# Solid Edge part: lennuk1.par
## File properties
Author: Priit
Template: Normal.par
Last saved by: Priit
Revision: 4
Application: Solid Edge
Accuracy: 0,990
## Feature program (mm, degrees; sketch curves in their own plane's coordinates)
sketch for "unnamed RevolvedProtrusion 1" plane through (0, 0, 0) normal (0, -1, 0) x-axis (1, 0, 0)
  bspline degree 3 poles (93.0645, 0) (25.9308, 33.3333) (-41.203, 33.3333) (-108.3368, 0) knots 0 1 multiplicities 4 4
  line (-108.3368, 0) -> (93.0645, 0)
revolve "unnamed RevolvedProtrusion 1" add finite 360 deg
lofted protrusion "unnamed LoftedProtrusion 1"
mirror "unnamed Mirror 1" of "unnamed LoftedProtrusion 1" about plane through (0, 0, 0) normal (0, -1, 0)
lofted protrusion "unnamed LoftedProtrusion 2"
lofted protrusion "unnamed LoftedProtrusion 3"
sketch used by "ExtrudedCutout_3" plane through (0, 0, 0) normal (0, -1, 0) x-axis (1, 0, 0)
extrude "ExtrudedCutout_3" cut finite 173.642 symmetric
sketch for "unnamed RevolvedCutout 1" plane through (0, 0, 0) normal (0, -1, 0) x-axis (1, 0, 0)
revolve "unnamed RevolvedCutout 1" cut finite 360 deg
sketch used by "ExtrudedCutout_5" plane through (0, 0, 0) normal (1, 0, 0) x-axis (0, 1, 0)
extrude "ExtrudedCutout_5" cut finite 149.25 along +normal
sketch for "ExtrudedProtrusion_1" plane through (-67.1627, -58.1792, 4) normal (-0.104528, -0.994522, 0) x-axis (0.993755, -0.104448, -0.039258)
  line (-13.2133, 2.9809) -> (11.7499, 4.4524)
  line (12.2198, -3.5199) -> (-13.0759, -4.0164)
extrude "ExtrudedProtrusion_1" add finite 4 along +normal
mirror "unnamed Mirror 2" of "ExtrudedProtrusion_1" about plane through (0, 0, 0) normal (0, -1, 0)
extrude "unnamed Protrusion 1" add finite 4
sketch for "ExtrudedCutout_6" plane through (0, 0, 0) normal (1, 0, 0) x-axis (0, 1, 0)
  circle centre (-31.8247, -0.6659) radius 2.0832
extrude "ExtrudedCutout_6" cut finite 26.1293 along -normal
mirror "unnamed Mirror 3" of "ExtrudedCutout_6" about plane through (0, 0, 0) normal (0, -1, 0)
extrude "unnamed Cutout 1" cut finite 26.1293
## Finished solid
Body 1: solid body, 38 faces, 91 edges, 58 vertices.
  Faces by surface: plane 16, spline 12, cylinder 7, spun 2, swept 1
  Edges by curve: line 32, intersection 30, circle 17, spline 12
Bounding box of the edges (mm; curved faces can reach further): 180.651 x 127.707 x 49.468, from (-99.7486, -63.8537, -4.4682) to (80.9029, 63.8537, 45).
Cylindrical faces by radius (mm): R2.0832 x2, R3.5 x2, R4 x2, R20.467 x1
Planar faces by outward normal: +x 2, +z 2, oblique 12
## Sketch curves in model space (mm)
circle centre (0, -31.8247, -0.6659) radius 2.0832
line (0, 7.2862, 19.1262) -> (0, 9.496, 5.6737)
arc centre (0, 0, 0) radius 20.467 from (0, -7.2862, 19.1262) through (0, 0, 20.467) to (0, 7.2862, 19.1262)
line (0, -7.2862, 19.1262) -> (0, -9.496, 5.6737)
line (0, -9.496, 5.6737) -> (0, 9.496, 5.6737)
line (-102.1983, 0, 0) -> (85.7441, 0, 0)
spline (-102.1983, 0, 0) -> (-7.9163, 0, 21.9859) -> (85.7441, 0, 0)
arc centre (-84.2075, 0, 45) radius 1 from (-84.274, 0.9978, 45) through (-83.2093, -0.0595, 45) to (-84.274, -0.9978, 45)
line (-84.274, -0.9978, 45) -> (-99.2486, -0.5, 45)
arc centre (-99.2486, 0, 45) radius 0.5 from (-99.2486, -0.5, 45) through (-99.7484, 0.0148, 45) to (-99.2486, 0.5, 45)
line (-99.2486, 0.5, 45) -> (-84.274, 0.9978, 45)
arc centre (-70.797, 0, 25) radius 2 from (-70.9773, 1.9919, 25) through (-68.7979, -0.0593, 25) to (-70.9773, -1.9919, 25)
line (-70.9773, -1.9919, 25) -> (-92.944, -1, 25)
arc centre (-92.944, 0, 25) radius 1 from (-92.944, -1, 25) through (-93.9435, 0.0296, 25) to (-92.944, 1, 25)
line (-92.944, 1, 25) -> (-70.9773, 1.9919, 25)
arc centre (-65.2645, 0, 0) radius 3 from (-65.7228, 2.9648, 0) through (-62.2698, -0.1783, 0) to (-65.7228, -2.9648, 0)
line (-65.7228, -2.9648, 0) -> (-91.293, -1, 0)
arc centre (-91.293, 0, 0) radius 1 from (-91.293, -1, 0) through (-92.2925, 0.0296, 0) to (-91.293, 1, 0)
line (-91.293, 1, 0) -> (-65.7228, 2.9648, 0)
arc centre (-80.3137, 56.797, 4) radius 1 from (-80.3137, 56.797, 3) through (-81.3078, 56.6925, 4.0296) to (-80.3137, 56.797, 5)
line (-80.3137, 56.797, 5) -> (-55.1565, 59.4411, 5.9938)
arc centre (-55.0005, 59.4575, 4) radius 2 from (-55.1565, 59.4411, 5.9938) through (-53.015, 59.6662, 3.8801) to (-55.1565, 59.4411, 2.0062)
line (-55.1565, 59.4411, 2.0062) -> (-80.3137, 56.797, 3)
arc centre (-24.3593, 40.2383, 0) radius 3 from (-24.3593, 40.2383, 3) through (-21.3618, 40.2383, -0.1233) to (-24.6057, 40.2383, -2.9899)
line (-24.6057, 40.2383, -2.9899) -> (-72.9777, 40.2383, -1)
arc centre (-72.9777, 40.2383, 0) radius 1 from (-72.9777, 40.2383, -1) through (-73.9772, 40.2383, 0.0296) to (-72.9777, 40.2383, 1)
line (-72.9777, 40.2383, 1) -> (-24.3593, 40.2383, 3)
arc centre (-0.1324, 0, 0) radius 4 from (-0.1324, 0, 4) through (3.8659, 0, -0.1185) to (-0.1324, 0, -4)
line (-0.1324, 0, -4) -> (-72.9982, 0, -1)
arc centre (-72.9982, 0, 0) radius 1 from (-72.9982, 0, -1) through (-73.9978, 0, 0.0296) to (-72.9982, 0, 1)
line (-72.9982, 0, 1) -> (-0.1324, 0, 4)
arc centre (-55.0005, -59.4575, 4) radius 4 from (-55.3124, -59.4247, 7.9877) through (-51.0255, -59.8753, 3.8414) to (-55.1566, -59.4411, 0.0031)
line (-55.1566, -59.4411, 0.0031) -> (-80.3138, -56.797, 0.5)
arc centre (-80.3137, -56.797, 4) radius 3.5 from (-80.3138, -56.797, 0.5) through (-83.7939, -56.4312, 4.0687) to (-80.1771, -56.8113, 7.4973)
line (-80.1771, -56.8113, 7.4973) -> (-55.3124, -59.4247, 7.9877)
line (12.4822, 0, 5.6737) -> (0, 0, 21.5602)
spline (0, 0, 21.5602) -> (33.2754, 0, 18.4931) -> (62.7893, 0, 5.6737)
line (62.7893, 0, 5.6737) -> (12.4822, 0, 5.6737)
spline (93.0645, 0, 0) -> (-7.6361, 0, 25) -> (-108.3368, 0, 0)
line (-108.3368, 0, 0) -> (93.0645, 0, 0)
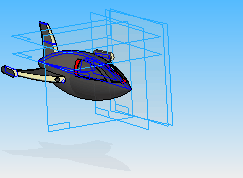
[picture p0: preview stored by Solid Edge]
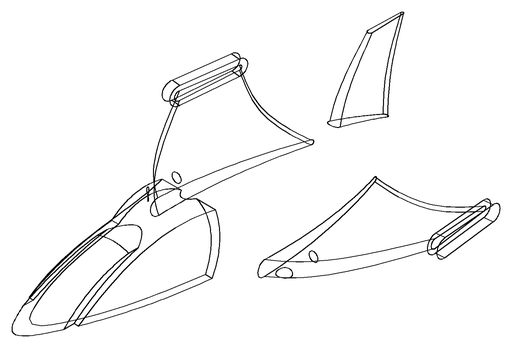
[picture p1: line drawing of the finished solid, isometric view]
